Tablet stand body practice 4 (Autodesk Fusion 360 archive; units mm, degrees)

design "mm-Tablet stand body practice 4" references "haas minimill"
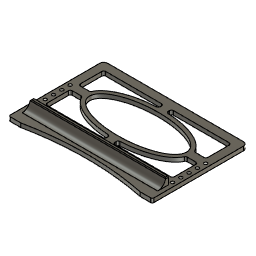
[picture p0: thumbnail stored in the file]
sketch "Sketch1" plane through (0, 0, 0) normal (0, 0, 1) x axis (1, 0, 0)
  line L1 (225.425, 0) -> (0, 0)
  line L2 (225.425, 149.225) -> (225.425, 0)
  line L3 (0, 149.225) -> (225.425, 149.225)
  line L4 (0, 0) -> (0, 149.225)
  point P1 (0, 0)
  point P2 (0, 0)
  point P3 (225.425, 0)
  point P5 (0, 149.225)
  horizontal L1
  vertical L2
  horizontal L3
  vertical L4
  coincident P1 P2
  dimension "d1" distance P2 P3 = 225.425
  dimension "d2" distance P2 P5 = 149.225
extrude "Extrude1" new body sketch "Sketch1" along normal blind 6.35
sketch "Sketch2" plane through (225.425, 0, 0) normal (1, 0, 0) x axis (0, 1, 0)
  line L1 (149.225, 0) -> (0, 0)
  line L2 (149.225, 6.35) -> (149.225, 0)
  line L3 (0, 6.35) -> (149.225, 6.35)
  line L4 (0, 0) -> (0, 6.35)
  line L5 (15.875, 6.35) -> (0, 6.35)
  line L6 (28.575, 6.35) -> (15.875, 6.35)
  line L7 (28.575, 17.907) -> (28.575, 6.35)
  line L8 (31.75, 17.907) -> (28.575, 17.907)
  line L9 (31.75, 6.35) -> (31.75, 17.907)
  line L10 (28.575, 6.35) -> (31.75, 6.35)
  line L11 (27.305, 6.35) -> (28.575, 6.35)
  line L12 (27.305, 16.637) -> (27.305, 6.35)
  line L13 (27.305, 16.637) -> (28.575, 17.907)
  line L14 (34.0111, 17.907) -> (28.575, 17.907)
  point P5 (0, 6.35)
  point P6 (0, 6.35)
  point P11 (31.75, 6.35)
  point P7 (15.875, 6.35)
  point P8 (28.575, 6.35)
  point P9 (28.575, 17.907)
  point P10 (31.75, 17.907)
  point P12 (27.305, 6.35)
  coincident P5 P6
  perpendicular L4 L5
  parallel L3 L6
  perpendicular L6 L7
  perpendicular L7 L8
  coincident L3 P11
  perpendicular L3 L9
  perpendicular L7 L11
  perpendicular L6 L12
  horizontal L14
  dimension "d5" distance P6 P7 = 15.875
  dimension "d6" distance P7 P8 = 12.7
  dimension "d8" distance P8 P9 = 11.557
  dimension "d9" distance P9 P10 = 3.175
  dimension "d10" distance P8 P12 = 1.27
  dimension "d11" angle L13 L14 = 135
extrude "Extrude2" add sketch "Sketch2" profile of L3 L6 L7 L8 L9 L10 L11 L12 L13 against normal blind 225.425
fillet "Fillet1" radius 12.7
sketch "Sketch3" plane through (0, 0, 6.35) normal (0, 0, 1) x axis (-1, 0, 0)
  line L1 (0, -14.8363) -> (-225.425, -14.8363)
  line L2 (0, 0) -> (0, -14.8363)
  line L3 (-225.425, 0) -> (0, 0)
  line L4 (-225.425, -14.8363) -> (-225.425, 0)
  line L5 (-19.05, 0) -> (0, 0)
  line L6 (-206.375, 0) -> (-225.425, 0)
  line L7 (-206.375, 0) -> (-19.05, 0)
  arc A1 centre (-112.7125, 457.2) radius 466.6953 clockwise from (-19.05, 0) to (-206.375, 0)
  point P4 (0, 0)
  point P6 (0, 0)
  point P5 (-225.425, 0)
  point P8 (-225.425, 0)
  point P7 (-19.05, 0)
  point P9 (-206.375, 0)
  point P10 (-112.7125, 457.2)
  coincident P4 P6
  perpendicular L2 L5
  coincident P5 P8
  perpendicular L4 L6
  dimension "d16" distance P6 P7 = 19.05
  dimension "d17" distance P8 P9 = 19.05
  dimension "d18" distance L3 P10 = 457.2
extrude "Extrude3" cut sketch "Sketch3" profile of L3 A1 L7 against normal blind 6.35
sketch "Sketch4" plane through (0, 0, 17.907) normal (0, 0, 1) x axis (-1, 0, 0)
  line L1 (-225.425, -31.75) -> (-225.425, -28.575)
  line L2 (0, -31.75) -> (-225.425, -31.75)
  line L3 (0, -28.575) -> (0, -31.75)
  line L4 (-225.425, -28.575) -> (0, -28.575)
  line L5 (-6.35, -31.75) -> (0, -31.75)
  line L6 (-6.35, -12.7) -> (-6.35, -31.75)
  line L7 (0, -12.7) -> (-6.35, -12.7)
  line L8 (0, -31.75) -> (0, -12.7)
  point P4 (0, -31.75)
  point P6 (0, -31.75)
  point P7 (-6.35, -31.75)
  point P9 (0, -12.7)
  horizontal L5
  vertical L6
  horizontal L7
  vertical L8
  coincident P4 P6
  dimension "d21" distance P6 P7 = 6.35
  dimension "d22" distance P6 P9 = 19.05
work_plane "WorkPlane1"
extrude "Extrude4" cut sketch "Sketch4" profile of L2 L3 L4 L5 L6 L7 L8 to an object
sketch "Sketch5" plane through (0, 0, 17.907) normal (0, 0, 1) x axis (-1, 0, 0)
  line L1 (-6.35, -28.575) -> (-6.35, -31.75)
  line L2 (-225.425, -28.575) -> (-6.35, -28.575)
  line L3 (-225.425, -31.75) -> (-225.425, -28.575)
  line L4 (-6.35, -31.75) -> (-225.425, -31.75)
  line L5 (-219.075, -31.75) -> (-225.425, -31.75)
  line L6 (-219.075, -12.7) -> (-219.075, -31.75)
  line L7 (-225.425, -12.7) -> (-219.075, -12.7)
  line L8 (-225.425, -31.75) -> (-225.425, -12.7)
  point P5 (-225.425, -31.75)
  point P6 (-225.425, -31.75)
  point P7 (-219.075, -31.75)
  point P9 (-225.425, -12.7)
  horizontal L5
  vertical L6
  horizontal L7
  vertical L8
  coincident P5 P6
  dimension "d25" distance P6 P7 = 6.35
  dimension "d26" distance P6 P9 = 19.05
extrude "Extrude5" cut sketch "Sketch5" profile of L2 L3 L4 L5 L6 L7 L8 to an object
chamfer "Chamfer1" distance 1.27
sketch "Sketch6" plane through (0, 0, 6.35) normal (0, 0, 1) x axis (-1, 0, 0)
  line L1 (-225.425, -149.225) -> (-225.425, 0)
  line L2 (0, -149.225) -> (-225.425, -149.225)
  line L3 (0, 0) -> (0, -149.225)
  line L4 (-19.05, 0) -> (0, 0)
  line L5 (-225.425, 0) -> (-206.375, 0)
  line L6 (-219.075, -14.8363) -> (-219.075, -31.75)
  line L7 (-6.35, -14.8363) -> (-219.075, -14.8363)
  line L8 (-6.35, -31.75) -> (-6.35, -14.8363)
  line L9 (-219.075, -31.75) -> (-6.35, -31.75)
  line L10 (-112.7125, -31.75) -> (-112.7125, -149.225)
  line L11 (-225.425, -90.4875) -> (-112.7125, -90.4875)
  curve K1 (-188.9125, -90.4875) -> (-36.5125, -90.4875)
  curve K2 (-112.7125, -122.2375) -> (-112.7125, -58.7375)
  arc A1 centre (-112.7125, 457.2) radius 466.6953 clockwise from (-19.05, 0) to (-206.375, 0)
  closed curve K3 centre (-112.7125, -90.4875)
  point P13 (-112.7125, -149.225)
  point P14 (-112.7125, -31.75)
  point P15 (-112.7125, -90.4875)
  point P18 (-36.5125, -90.4875)
  point P19 (-188.9125, -90.4875)
  point P20 (-112.7125, -58.7375)
  point P21 (-112.7125, -122.2375)
  point P17 (-112.7125, -90.4875)
  point P16 (-225.425, -90.4875)
  midpoint L2 P13
  midpoint L9 P14
  midpoint L10 P15
  perpendicular L10 L11
  coincident K3 P18
  coincident K3 P19
  coincident K3 P20
  coincident K3 P21
  coincident P15 P17
  perpendicular L10 K1
  coincident L1 P16
  dimension "d37" distance K3 = 152.4
  dimension "d38" = 31.75
extrude "Extrude6" cut sketch "Sketch6" profile of L10 L11 K3 no distance stored
sketch "Sketch7" plane through (0, 0, 6.35) normal (0, 0, 1) x axis (-1, 0, 0)
  line L1 (-212.725, -136.525) -> (-12.7, -136.525)
  line L2 (-212.725, -44.45) -> (-212.725, -136.525)
  line L3 (-12.7, -44.45) -> (-212.725, -44.45)
  line L4 (-12.7, -136.525) -> (-12.7, -44.45)
  line L5 (-225.425, -149.225) -> (-225.425, 0)
  line L6 (0, -149.225) -> (-225.425, -149.225)
  line L7 (0, 0) -> (0, -149.225)
  line L8 (-19.05, 0) -> (0, 0)
  line L9 (-225.425, 0) -> (-206.375, 0)
  line L10 (-219.075, -14.8363) -> (-219.075, -31.75)
  line L11 (-6.35, -14.8363) -> (-219.075, -14.8363)
  line L12 (-6.35, -31.75) -> (-6.35, -14.8363)
  line L13 (-219.075, -31.75) -> (-6.35, -31.75)
  line L14 (-106.3625, -90.4875) -> (-112.7125, -90.4875)
  line L15 (-112.7125, -44.45) -> (-112.7125, -90.4875)
  line L16 (-112.7125, -136.525) -> (-112.7125, -90.4875)
  line L17 (-106.3625, -84.1375) -> (-106.3625, -90.4875)
  line L18 (-106.3625, -44.45) -> (-106.3625, -52.5004)
  line L19 (-119.0625, -84.1375) -> (-119.0625, -90.4875)
  line L20 (-119.0625, -44.45) -> (-119.0625, -52.5004)
  line L21 (-106.3625, -122.1271) -> (-106.3625, -90.4875)
  line L22 (-106.3625, -136.525) -> (-106.3625, -128.4746)
  line L23 (-119.0625, -122.1271) -> (-119.0625, -90.4875)
  line L24 (-119.0625, -136.525) -> (-119.0625, -128.4746)
  line L25 (-119.0625, -84.1375) -> (-112.7125, -84.1375)
  line L26 (-212.725, -84.1375) -> (-194.1079, -84.1375)
  line L27 (-119.0625, -96.8375) -> (-112.7125, -96.8375)
  line L28 (-212.725, -96.8375) -> (-194.1079, -96.8375)
  line L29 (-119.0625, -90.4875) -> (-112.7125, -90.4875)
  line L30 (-195.2625, -90.4875) -> (-188.9125, -90.4875)
  line L31 (-38.0521, -84.1375) -> (-112.7125, -84.1375)
  line L32 (-12.7, -84.1375) -> (-31.3171, -84.1375)
  line L33 (-38.0521, -96.8375) -> (-112.7125, -96.8375)
  line L34 (-12.7, -96.8375) -> (-31.3171, -96.8375)
  closed curve K1 centre (-112.7125, -90.4875)
  arc A1 centre (-112.7125, 457.2) radius 466.6953 clockwise from (-19.05, 0) to (-206.375, 0)
  closed curve K2 centre (-112.7125, -90.4875)
  closed curve K3 centre (-112.7125, -90.4875)
  point P6 (-112.7125, -90.4875)
  point P20 (-112.7125, -90.4875)
  point P18 (-112.7125, -90.4875)
  point P21 (-112.7125, -90.4875)
  point P22 (-112.7125, -44.45)
  point P23 (-112.7125, -90.4875)
  point P24 (-112.7125, -136.525)
  point P39 (-106.3625, -84.1375)
  point P41 (-119.0625, -52.5004)
  point P42 (-106.3625, -52.5004)
  point P43 (-106.3625, -122.1271)
  point P44 (-106.3625, -128.4746)
  point P45 (-119.0625, -122.1271)
  point P46 (-119.0625, -128.4746)
  point P47 (-119.0625, -96.8375)
  point P48 (-194.1079, -96.8375)
  point P49 (-194.1079, -84.1375)
  point P50 (-188.9125, -90.4875)
  point P51 (-195.2625, -90.4875)
  point P52 (-38.0521, -84.1375)
  point P53 (-31.3171, -84.1375)
  point P54 (-38.0521, -96.8375)
  point P55 (-31.3171, -96.8375)
  horizontal L1
  vertical L2
  horizontal L3
  vertical L4
  coincident P6 P20
  perpendicular L2 L29
  coincident P18 P21
  midpoint L3 P22
  perpendicular L3 L15
  coincident P18 P23
  midpoint L1 P24
  coincident P39 L31
  collinear L17 L18
  collinear L19 L20
  coincident K3 P41
  coincident K3 P42
  coincident K1 P43
  coincident K3 P44
  collinear L21 L22
  coincident K1 P45
  coincident K3 P46
  collinear L23 L24
  collinear L25 L26
  coincident L23 P47
  collinear L27 L28
  coincident K3 P48
  coincident K3 P49
  coincident K1 P50
  collinear L29 L30
  coincident K3 P51
  coincident K1 P52
  coincident K3 P53
  collinear L31 L32
  coincident K1 P54
  coincident K3 P55
  collinear L33 L34
  dimension "d65" distance L1 L6 = 12.7
  dimension "d66" distance L2 L5 = 12.7 (= "d65")
  dimension "d67" distance L3 L13 = 12.7
  dimension "d68" = 38.1
extrude "Extrude7" cut sketch "Sketch7" profile of L1 L2 L3 L4 K3 L24 L22 L26 L32 L28 L34 L18 L20 no distance stored
fillet "Fillet2" radius 3
fillet "Fillet3" radius 3
hole "Hole1" HoleDepth 35.56 HoleDiameter 5.035 TipAngle 118 RefDim1 6.35 RefDim2 38.1
rectangular_pattern "R-Pattern1" uSpaceDistance -52.07 vSpaceDistance 212.725
fillet "Fillet4" radius 6
fillet "Fillet5" radius 2.5
fillet "Fillet6" radius 2.5
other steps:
thread "Thread1"

design "haas minimill"
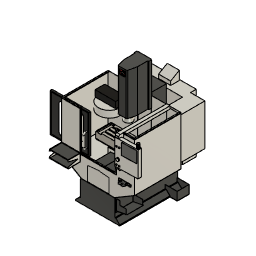
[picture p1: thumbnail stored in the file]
